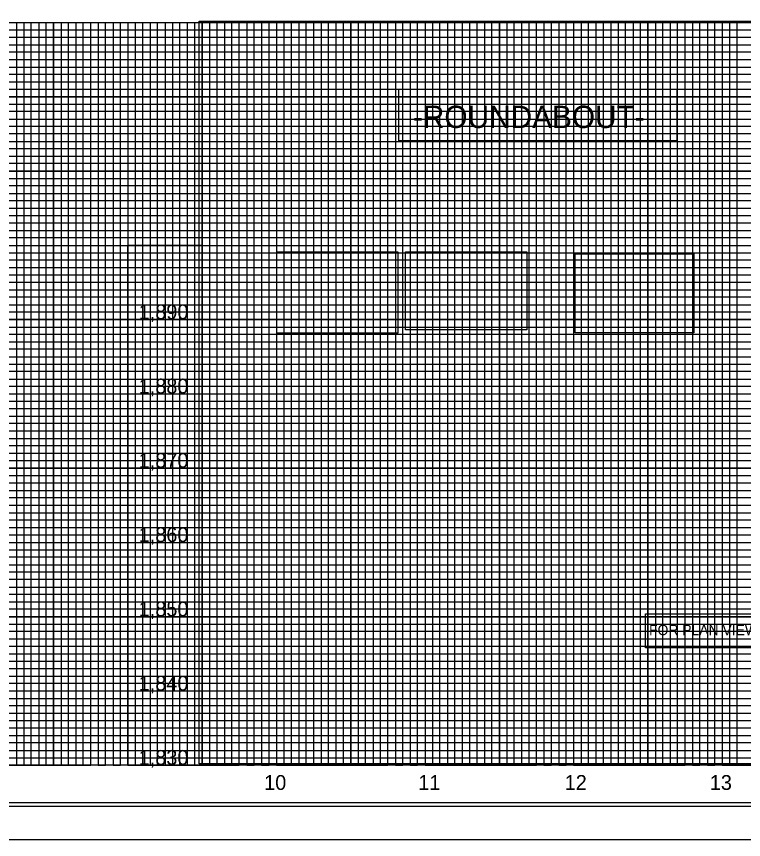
# Model space of a CAD drawing. Extents: x 557032 to 558716, y 525869 to 526969.
# Drawn here: x 557874 to 558364, y 525869 to 526423 of the extents above; entities that cross this region are included whole.
import ezdxf

# ---------------------------------------------------------------- set-up
doc = ezdxf.new("R2010")
doc.units = 0
for name, color, linetype in [('Exist Vertical Profile Horizontal Axis Label Major', 7, 'Continuous'), ('Exist Vertical Profile Vertical Axis Label', 7, 'Continuous'), ('Old_Level_63', 7, 'Continuous'), ('Prop Vertical Profile Curve Label', 7, 'Continuous'), ('Prop Vertical Profile Grade Label', 7, 'Continuous'), ('Prop VPI Label', 7, 'Continuous'), ('Scratch_Level_5', 7, 'Continuous'), ('Sheet Cutting Line CELL', 7, 'Continuous'), ('Sheet DOT Grid CELL', 7, 'Continuous'), ('Sheet Layout Profile Border Port 2', 7, 'Continuous'), ('Sheet Plot Border Inside CELL', 7, 'Continuous'), ('Sheet Plot Border Outside CELL', 7, 'Continuous'), ('Sheet Profile CELL', 7, 'Continuous'), ('Sheet Profile Grid Major CELL', 7, 'Continuous'), ('Sheet Profile Grid Middle CELL', 7, 'Continuous'), ('Sheet Profile Grid Minor CELL', 7, 'Continuous')]:
    doc.layers.add(name, color=color, linetype=linetype)

msp = doc.modelspace()

# ---------------------------------------------------------------- linework, layer by layer
at = {"layer": 'Old_Level_63'}
msp.add_lwpolyline([(557949.45, 526269.22), (557999.45, 526269.22), (557999.45, 525919.22), (557949.45, 525919.22)], close=True, dxfattribs=at)
at = {"layer": 'Prop Vertical Profile Curve Label'}
for points in [[(558131.8, 526374.3), (558318.88, 526374.3), (558318.88, 526339.67), (558131.8, 526339.67)], [(558131.8, 526374.3), (558318.88, 526374.3), (558318.88, 526339.67), (558131.8, 526339.67)], [(558049.58, 526264.9), (558131.12, 526264.9), (558131.12, 526210.06), (558049.58, 526210.06)], [(558136.33, 526264.9), (558217.96, 526264.9), (558217.96, 526212.3), (558136.33, 526212.3)], [(558250.46, 526263.44), (558330.34, 526263.44), (558330.34, 526210.36), (558250.46, 526210.36)]]:
    msp.add_lwpolyline(points, close=True, dxfattribs=at)
at = {"layer": 'Prop VPI Label'}
for points in [[(558131.8, 526374.3), (558318.88, 526374.3), (558318.88, 526339.67), (558131.8, 526339.67)], [(558297.78, 526021.14), (558468.92, 526021.14), (558468.92, 525998.23), (558297.78, 525998.23)], [(558297.78, 526021.14), (558468.92, 526021.14), (558468.92, 525998.23), (558297.78, 525998.23)]]:
    msp.add_lwpolyline(points, close=True, dxfattribs=at)
at = {"layer": 'Scratch_Level_5'}
msp.add_lwpolyline([(557997.44, 526420.09), (558512.44, 526420.09), (558512.49, 525920.09), (557997.49, 525920.09)], close=True, dxfattribs=at)
at = {"layer": 'Sheet Cutting Line CELL'}
msp.add_line((557032.45, 525869.22), (558716.45, 525869.22), dxfattribs=at)
at = {"layer": 'Sheet DOT Grid CELL'}
for p, q in [((557199.45, 526419.22), (558699.34, 526419.22)), ((557899.45, 526419.22), (557899.45, 525919.22)), ((557949.45, 526419.22), (557949.45, 525919.22)), ((557999.45, 526419.22), (557999.45, 525919.22)), ((558049.45, 526419.22), (558049.45, 525919.22)), ((558099.45, 526419.22), (558099.45, 525919.22)), ((558149.45, 526419.22), (558149.45, 525919.22)), ((558199.45, 526419.22), (558199.45, 525919.22)), ((558249.45, 526419.22), (558249.45, 525919.22)), ((558299.45, 526419.22), (558299.45, 525919.22)), ((558349.45, 526419.22), (558349.45, 525919.22)), ((557199.45, 526369.22), (558699.34, 526369.22)), ((557199.45, 526319.22), (558699.34, 526319.22)), ((557199.45, 526269.22), (558699.34, 526269.22)), ((557199.45, 526219.22), (558699.34, 526219.22)), ((557199.45, 526169.22), (558699.34, 526169.22)), ((557199.45, 526119.22), (558699.34, 526119.22)), ((557199.45, 526069.22), (558699.34, 526069.22)), ((557199.45, 526019.22), (558699.34, 526019.22)), ((557199.45, 525969.22), (558699.34, 525969.22))]:
    msp.add_line(p, q, dxfattribs=at)
at = {"layer": 'Sheet Layout Profile Border Port 2'}
msp.add_lwpolyline([(557249.45, 526419.22), (558649.45, 526419.22), (558649.45, 525919.22), (557249.45, 525919.22)], close=True, dxfattribs=at)
at = {"layer": 'Sheet Plot Border Inside CELL'}
msp.add_lwpolyline([(557045.45, 525891.67), (558711.95, 525891.67), (558711.95, 526946.77), (557045.45, 526946.77)], close=True, dxfattribs=at)
at = {"layer": 'Sheet Plot Border Outside CELL'}
msp.add_lwpolyline([(557032.45, 525869.22), (558716.45, 525869.22), (558716.45, 526969.22), (557032.45, 526969.22)], close=True, dxfattribs=at)
at = {"layer": 'Sheet Profile CELL'}
for p, q in [((557199.45, 526419.22), (558699.45, 526419.22)), ((558699.45, 525919.22), (557199.45, 525919.22)), ((557199.45, 525894.22), (558699.45, 525894.22))]:
    msp.add_line(p, q, dxfattribs=at)
msp.add_lwpolyline([(558699.45, 526944.22), (557199.45, 526944.22), (557199.45, 525894.22), (558699.45, 525894.22)], close=True, dxfattribs=at)
at = {"layer": 'Sheet Profile Grid Major CELL'}
for p, q in [((557899.45, 526419.22), (557949.45, 526419.22)), ((557999.45, 526419.22), (558049.45, 526419.22)), ((558099.45, 526419.22), (558149.45, 526419.22)), ((558199.45, 526419.22), (558249.45, 526419.22)), ((558299.45, 526419.22), (558349.45, 526419.22)), ((557949.45, 526219.22), (557999.45, 526219.22)), ((557949.45, 526219.22), (557999.45, 526219.22)), ((557949.45, 526169.22), (557999.45, 526169.22)), ((557949.45, 526169.22), (557999.45, 526169.22)), ((557949.45, 526119.22), (557999.45, 526119.22)), ((557949.45, 526119.22), (557999.45, 526119.22)), ((557949.45, 526069.22), (557999.45, 526069.22)), ((557949.45, 526069.22), (557999.45, 526069.22)), ((557949.45, 526019.22), (557999.45, 526019.22)), ((557949.45, 526019.22), (557999.45, 526019.22)), ((557949.45, 525969.22), (557999.45, 525969.22)), ((557949.45, 525969.22), (557999.45, 525969.22))]:
    msp.add_line(p, q, dxfattribs=at)
for points in [[(557849.45, 525919.22), (557899.45, 525919.22), (557899.45, 526419.22), (557949.45, 526419.22), (557949.45, 525919.22), (557999.45, 525919.22), (557999.45, 526419.22), (558049.45, 526419.22), (558049.45, 525919.22), (558099.45, 525919.22), (558099.45, 526419.22), (558149.45, 526419.22), (558149.45, 525919.22), (558199.45, 525919.22), (558199.45, 526419.22), (558249.45, 526419.22), (558249.45, 525919.22), (558299.45, 525919.22), (558299.45, 526419.22), (558349.45, 526419.22), (558349.45, 525919.22), (558399.45, 525919.22)], [(558699.45, 526369.22), (557199.45, 526369.22)], [(558699.45, 526319.22), (557199.45, 526319.22), (557199.45, 526269.22), (558699.45, 526269.22)], [(558699.45, 526219.22), (557199.45, 526219.22), (557199.45, 526169.22), (558699.45, 526169.22)], [(558699.45, 526119.22), (557199.45, 526119.22), (557199.45, 526069.22), (558699.45, 526069.22)], [(558699.45, 526019.22), (557199.45, 526019.22), (557199.45, 526019.22), (557199.45, 525969.22), (558699.45, 525969.22)], [(558699.45, 525919.22), (557199.45, 525919.22)]]:
    msp.add_lwpolyline(points, dxfattribs=at)
msp.add_lwpolyline([(557949.45, 525919.22), (557999.45, 525919.22), (557999.45, 526269.22), (557949.45, 526269.22)], close=True, dxfattribs=at)
msp.add_lwpolyline([(557949.45, 525919.22), (557999.45, 525919.22), (557999.45, 526269.22), (557949.45, 526269.22)], close=True, dxfattribs=at)
at = {"layer": 'Sheet Profile Grid Middle CELL'}
for points in [[(557824.45, 526419.22), (557874.45, 526419.22), (557874.45, 525919.22), (557924.45, 525919.22), (557924.45, 526419.22), (557974.45, 526419.22), (557974.45, 525919.22), (558024.45, 525919.22), (558024.45, 526419.22), (558074.45, 526419.22), (558074.45, 525919.22), (558124.45, 525919.22), (558124.45, 526419.22), (558174.45, 526419.22), (558174.45, 525919.22), (558224.45, 525919.22), (558224.45, 526419.22), (558274.45, 526419.22), (558274.45, 525919.22), (558324.45, 525919.22), (558324.45, 526419.22), (558374.45, 526419.22)], [(557199.45, 526394.22), (558699.45, 526394.22)], [(558699.45, 526344.22), (557199.45, 526344.22), (557199.45, 526294.22), (558699.45, 526294.22)], [(558699.45, 526244.22), (557199.45, 526244.22), (557199.45, 526194.22), (558699.45, 526194.22)], [(558699.45, 526144.22), (557199.45, 526144.22), (557199.45, 526094.22), (558699.45, 526094.22)], [(558546.09, 526044.22), (557199.45, 526044.22), (557199.45, 525994.22), (558699.45, 525994.22)], [(558699.45, 525944.22), (557199.45, 525944.22)]]:
    msp.add_lwpolyline(points, dxfattribs=at)
at = {"layer": 'Sheet Profile Grid Minor CELL'}
for p, q in [((557249.45, 526414.22), (558649.45, 526414.22)), ((558649.45, 526409.22), (557249.45, 526409.22)), ((557249.45, 526404.22), (558649.45, 526404.22)), ((558649.45, 526399.22), (557249.45, 526399.22)), ((557249.45, 526389.22), (558649.45, 526389.22)), ((558649.45, 526384.22), (557249.45, 526384.22)), ((557249.45, 526379.22), (558649.45, 526379.22)), ((558649.45, 526374.22), (557249.45, 526374.22)), ((557249.45, 526364.22), (558649.45, 526364.22)), ((558649.45, 526359.22), (557249.45, 526359.22)), ((557249.45, 526354.22), (558649.45, 526354.22)), ((558649.45, 526349.22), (557249.45, 526349.22)), ((557249.45, 526339.22), (558649.45, 526339.22)), ((558649.45, 526334.22), (557249.45, 526334.22)), ((557249.45, 526329.22), (558649.45, 526329.22)), ((558649.45, 526324.22), (557249.45, 526324.22)), ((557249.45, 526314.22), (558649.45, 526314.22)), ((558649.45, 526309.22), (557249.45, 526309.22)), ((557249.45, 526304.22), (558649.45, 526304.22)), ((558649.45, 526299.22), (557249.45, 526299.22)), ((557249.45, 526289.22), (558649.45, 526289.22)), ((558649.45, 526284.22), (557249.45, 526284.22)), ((557249.45, 526279.22), (558649.45, 526279.22)), ((558649.45, 526274.22), (557249.45, 526274.22)), ((557249.45, 526264.22), (558649.45, 526264.22)), ((558649.45, 526259.22), (557249.45, 526259.22)), ((557249.45, 526254.22), (558649.45, 526254.22)), ((558649.45, 526249.22), (557249.45, 526249.22)), ((557249.45, 526239.22), (558649.45, 526239.22)), ((558649.45, 526234.22), (557249.45, 526234.22)), ((557249.45, 526229.22), (558649.45, 526229.22)), ((558649.45, 526224.22), (557249.45, 526224.37)), ((557249.45, 526214.22), (558649.45, 526214.22)), ((558649.45, 526209.22), (557249.45, 526209.22)), ((557249.45, 526204.22), (558649.45, 526204.22)), ((558649.45, 526199.22), (557249.45, 526199.22)), ((557249.45, 526189.22), (558649.45, 526189.22)), ((558649.45, 526184.22), (557249.45, 526184.22)), ((557249.45, 526179.22), (558649.45, 526179.22)), ((558649.45, 526174.22), (557249.45, 526174.22)), ((557249.45, 526164.22), (558649.45, 526164.22)), ((558649.45, 526159.22), (557249.45, 526159.22)), ((557249.45, 526154.22), (558649.45, 526154.22)), ((558649.45, 526149.22), (557249.45, 526149.22)), ((557249.45, 526139.22), (558649.45, 526139.22)), ((558649.45, 526134.22), (557249.45, 526134.22)), ((557249.45, 526129.22), (558649.45, 526129.22)), ((558649.45, 526124.22), (557249.45, 526124.22)), ((557249.45, 526114.22), (558649.45, 526114.22)), ((558649.45, 526109.22), (557249.45, 526109.22)), ((557249.45, 526104.22), (558649.45, 526104.22)), ((558649.45, 526099.22), (557249.45, 526099.22)), ((557249.45, 526089.22), (558649.45, 526089.22)), ((558649.45, 526084.22), (557249.45, 526084.22)), ((557249.45, 526079.22), (558649.45, 526079.22)), ((558649.45, 526074.22), (557249.45, 526074.22)), ((557249.45, 526064.22), (558649.45, 526064.22)), ((558649.45, 526059.22), (557249.45, 526059.22)), ((557249.45, 526054.22), (558649.45, 526054.22)), ((558649.45, 526049.22), (557249.45, 526049.22)), ((557249.45, 526039.22), (558546.09, 526039.22)), ((558546.09, 526034.22), (557249.45, 526034.22)), ((557249.45, 526029.22), (558546.09, 526029.22)), ((558546.09, 526024.22), (557249.45, 526024.22)), ((557249.45, 526014.22), (558649.45, 526014.22)), ((558649.45, 526009.22), (557249.45, 526009.22)), ((557249.45, 526004.22), (558649.45, 526004.22)), ((558649.45, 525999.22), (557249.45, 525999.22)), ((557249.45, 525989.22), (558649.45, 525989.22)), ((558649.45, 525984.22), (557249.45, 525984.22)), ((557249.45, 525979.22), (558649.45, 525979.22)), ((558649.45, 525974.22), (557249.45, 525974.22)), ((557249.45, 525964.22), (558649.45, 525964.22)), ((558649.45, 525959.22), (557249.45, 525959.22)), ((557249.45, 525954.22), (558649.45, 525954.22)), ((558649.45, 525949.22), (557249.45, 525949.22)), ((557249.45, 525939.22), (558649.45, 525939.22)), ((558649.45, 525934.22), (557249.45, 525934.22)), ((557249.45, 525929.22), (558649.45, 525929.22)), ((557249.45, 525924.22), (558649.45, 525924.22))]:
    msp.add_line(p, q, dxfattribs=at)
for points in [[(557869.45, 526419.22), (557879.45, 526419.22), (557879.45, 525919.22), (557884.45, 525919.22), (557884.45, 526419.22), (557889.45, 526419.22), (557889.45, 525919.22), (557894.45, 525919.22), (557894.45, 526419.22), (557904.45, 526419.22), (557904.45, 525919.22), (557904.45, 525919.22), (557909.45, 525919.22), (557909.45, 526419.22), (557914.45, 526419.22), (557914.45, 525919.22), (557919.45, 525919.22), (557919.45, 526419.22), (557929.45, 526419.22), (557929.45, 525919.22), (557934.45, 525919.22), (557934.45, 526419.22), (557939.45, 526419.22), (557939.45, 525919.22), (557944.45, 525919.22), (557944.45, 526419.22), (557954.45, 526419.22), (557954.45, 525919.22), (557959.45, 525919.22), (557959.45, 526419.22), (557964.45, 526419.22), (557964.45, 525919.22), (557969.45, 525919.22), (557969.45, 526419.22), (557979.45, 526419.22), (557979.45, 525919.22), (557984.45, 525919.22), (557984.45, 526419.22), (557989.45, 526419.22), (557989.45, 525919.22), (557994.45, 525919.22), (557994.45, 526419.22), (558004.45, 526419.22), (558004.45, 525919.22), (558009.45, 525919.22), (558009.45, 526419.22), (558014.45, 526419.22), (558014.45, 525919.22), (558019.45, 525919.22), (558019.45, 526419.22), (558029.45, 526419.22), (558029.45, 525919.22), (558034.45, 525919.22), (558034.45, 526419.22), (558039.45, 526419.22), (558039.45, 525919.22), (558044.45, 525919.22), (558044.45, 526419.22), (558054.45, 526419.22), (558054.45, 525919.22), (558059.15, 525919.77), (558059.45, 525919.22), (558059.45, 526419.22), (558064.45, 526419.22), (558064.45, 525919.22), (558069.45, 525919.22), (558069.45, 526419.22), (558079.45, 526419.22), (558079.45, 525919.22), (558084.45, 525919.22)], [(558084.45, 525919.22), (558084.45, 526419.22), (558089.45, 526419.22), (558089.45, 525919.22), (558094.45, 525919.22), (558094.45, 526419.22), (558104.45, 526419.22), (558104.45, 525919.22), (558109.45, 525919.22), (558109.45, 526419.22), (558114.45, 526419.22), (558114.45, 525919.22), (558119.45, 525919.22), (558119.45, 526419.22), (558129.45, 526419.22), (558129.45, 525919.22), (558134.45, 525919.22), (558134.45, 526419.22), (558139.45, 526419.22), (558139.45, 525919.22), (558144.45, 525919.22), (558144.45, 526419.22), (558154.45, 526419.22), (558154.45, 525919.22), (558159.45, 525919.22), (558159.45, 526419.22), (558164.45, 526419.22), (558164.45, 525919.22), (558169.45, 525919.22), (558169.45, 526419.22), (558179.45, 526419.22), (558179.45, 525919.22), (558184.45, 525919.22), (558184.45, 526419.22), (558189.45, 526419.22), (558189.45, 525919.22), (558194.45, 525919.22), (558194.45, 526419.22), (558204.45, 526419.22), (558204.45, 525919.22), (558209.45, 525919.22), (558209.45, 526419.22), (558214.45, 526419.22), (558214.45, 525919.22), (558219.45, 525919.22), (558219.45, 526419.22), (558229.45, 526419.22), (558229.45, 525919.22), (558234.45, 525919.22), (558234.45, 526419.22), (558239.45, 526419.22), (558239.45, 525919.22), (558244.45, 525919.22), (558244.45, 526419.22), (558254.45, 526419.22), (558254.45, 525919.22), (558259.45, 525919.22), (558259.45, 526419.22), (558264.45, 526419.22), (558264.45, 525919.22), (558269.45, 525919.22), (558269.45, 526419.22), (558279.45, 526419.22), (558279.45, 525919.22), (558284.45, 525919.22), (558284.45, 526419.22), (558289.45, 526419.22), (558289.45, 525919.22), (558294.45, 525919.22), (558294.45, 526419.22), (558304.45, 526419.22), (558304.45, 525919.22), (558309.45, 525919.22), (558309.45, 526419.22), (558314.45, 526419.22), (558314.45, 525919.22), (558319.45, 525919.22), (558319.45, 526419.22), (558329.45, 526419.22), (558329.45, 525919.22), (558334.45, 525919.22), (558334.45, 526419.22), (558339.45, 526419.22), (558339.45, 525919.22), (558344.45, 525919.22), (558344.45, 526419.22), (558354.45, 526419.22), (558354.45, 525919.22), (558359.45, 525919.22), (558359.45, 526419.22), (558364.45, 526419.22)]]:
    msp.add_lwpolyline(points, dxfattribs=at)

# ---------------------------------------------------------------- texts
at = {"layer": 'Exist Vertical Profile Horizontal Axis Label Major'}
for s, p in [('10', (558041.16, 525902.63)), ('11', (558144.88, 525902.63)), ('12', (558243.43, 525902.63)), ('13', (558341.09, 525902.63))]:
    msp.add_text(s, height=10, dxfattribs=at).set_placement(p)
at = {"layer": 'Exist Vertical Profile Vertical Axis Label'}
for s, p in [('1,890', (557956.73, 526219.47)), ('1,880', (557956.73, 526169.47)), ('1,870', (557956.73, 526119.47)), ('1,860', (557956.73, 526069.47)), ('1,850', (557956.73, 526019.47)), ('1,840', (557956.73, 525969.47)), ('1,830', (557956.73, 525919.47))]:
    msp.add_text(s, height=10, dxfattribs=at).set_placement(p)
at = {"layer": 'Prop Vertical Profile Grade Label'}
msp.add_text('-ROUNDABOUT-', height=15, dxfattribs=at).set_placement((558141.29, 526348.21))
at = {"layer": 'Prop VPI Label'}
msp.add_text('FOR PLAN VIEW SEE SHEET 8', height=7, dxfattribs=at).set_placement((558300.21, 526006.79))

doc.saveas('drawing.dxf')
